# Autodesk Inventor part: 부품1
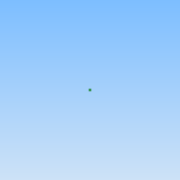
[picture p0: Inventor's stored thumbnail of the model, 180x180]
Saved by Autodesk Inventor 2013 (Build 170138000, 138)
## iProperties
Created: 2019-11
Part Number: 부품1
Material: Generic
Document SubType Name: Modeling
Designer: Administrator
Density: 1 g/cm^3
Author: Administrator
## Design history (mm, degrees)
sketch "스케치1"
  geometry: 1 further point
  constraints: 1 other
